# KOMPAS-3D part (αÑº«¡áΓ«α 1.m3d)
File: created 06.04.2016 12:01:11, last saved 07.04.2016 10:01:11.
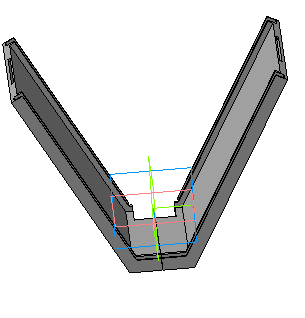
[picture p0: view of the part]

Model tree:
1. Эскиз:1
2. Операция выдавливания:1
     Толщина стенки 1 = 2; Толщина стенки 2 = 6; Расстояние 1 = 1
3. Эскиз:2
4. Операция выдавливания:2
     Толщина стенки 1 = 2; Толщина стенки 2 = 7; Расстояние 1 = 5
5. Эскиз:3
6. Операция выдавливания:3
     Толщина стенки 1 = 2; Толщина стенки 2 = 6; Расстояние 1 = 2
7. Эскиз:4
8. Операция выдавливания:4
     Толщина стенки 1 = 2; Толщина стенки 2 = 2.5; Расстояние 1 = 60
9. Эскиз:5
10. Вырезать элемент выдавливания:1
     Толщина стенки 2 = 1.5; Расстояние 1 = 40
11. Эскиз:6
12. Операция выдавливания:5
     Толщина стенки 1 = 2; Толщина стенки 2 = 2.5; Расстояние 1 = 20
13. Эскиз:7
14. Операция выдавливания:6
     Толщина стенки 1 = 2; Толщина стенки 2 = 6; Расстояние 1 = 2
15. Эскиз:8
16. Операция выдавливания:7
     Толщина стенки 1 = 2; Толщина стенки 2 = 6; Расстояние 1 = 5
17. Эскиз:9
18. Операция выдавливания:8
     Толщина стенки 1 = 2; Толщина стенки 2 = 6; Расстояние 1 = 1
19. Эскиз:10
20. Вырезать элемент выдавливания:2
     Толщина стенки 2 = 1.5; Расстояние 1 = 22
21. Эскиз:11
22. Вырезать элемент выдавливания:3
     Толщина стенки 2 = 1.5; Расстояние 1 = 1
23. Скругление:4
     Радиус = 1
24. Эскиз:12
25. Вырезать элемент выдавливания:4
     Расстояние 1 = 110
26. Эскиз:13
27. Вырезать элемент выдавливания:5
     Толщина стенки 1 = 0.1; Расстояние 1 = 20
